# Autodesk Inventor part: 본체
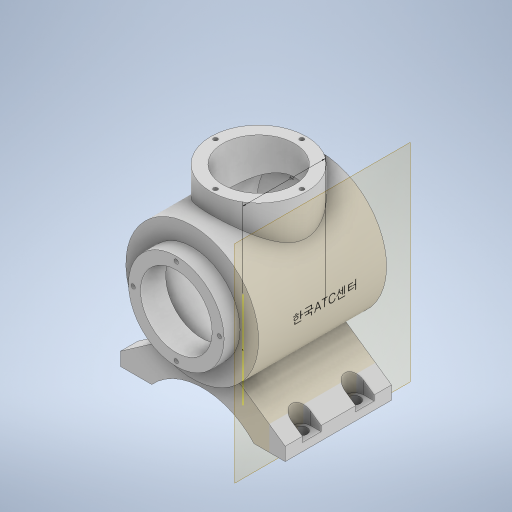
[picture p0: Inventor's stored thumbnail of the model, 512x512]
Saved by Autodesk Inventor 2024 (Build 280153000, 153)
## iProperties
Created: 2023-08
Part Number: 본체
Material: 일반
Document SubType Name: Modeling
Designer: Owner
Density: 1 g/cm^3
Appearance: 기본값
Author: Owner
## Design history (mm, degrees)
sketch "스케치1"
  geometry: L1 (36, 0)-(36, -12); L2 (36, -12)-(50, -12); L3 (50, -12)-(50, -108.336); L4 (0, 0)-(0, -120); L5 (27, -19)-(43, -19); L6 (43, -19)-(43, -103.887); L7 (27, -19)-(27, 0); L8 (27, 0)-(36, 0); A1 r 113 centre (0, -7) between (0, -120) and (50, -108.336); A2 r 106 centre (0, -7) between (0, -113) and (43, -103.887)
  constraints: 16 end point, 4 perpendicular, 4 point on circle, 2 centre point, 2 point on line, 2 vertical, 1 horizontal alignment, 2 other
  dimensions: "d0" = 100 diameter of L3 L4; "d1" = 72 diameter of L1 L4; "d2" = 113 radius of A1; "d5" = 7 radial gap between concentric circles of A1 A2; "d6" = 54 diameter of L7 L4; "d7" = 120 vertical distance of L4.end L1.start; "d9" = 108 distance from line of L4.end L2
revolve "회전1" sketch "스케치1" stored, may be unused: angle "d8" = 90 deg
node "작업 평면1"
sketch "스케치2"
  geometry: C1 r 36 at (0, -62); 1 further point
  constraints: 1 centre point, 1 vertical alignment
  dimensions: "d11" = 72 diameter of C1; "d12" = 62 distance of point (0, 0) C1.centre
extrude "돌출1" join sketch "스케치2" stored distance "d13" = 10; taper "d14" = 0 deg
sketch "스케치3"
  geometry: C1 r 36 at (0, 0) reference; C2 r 27 at (0, 0); 1 further point
  constraints: 1 centre point, 1 coincident
  dimensions: "d15" = 54 diameter of C2
extrude "돌출2" cut sketch "스케치3" stored distance "d16" = 10; taper "d17" = 0 deg
node "작업 평면2"
sketch "스케치4"
  geometry: L1 (-26.694, -42.278)-(-62, -67); L2 (-62, -67)-(-62, -77); L3 (62, -77)-(62, -67); L4 (62, -67)-(26.694, -42.278); L5 (36, 65)-(-36, 65) reference; L6 (-62, -77)-(-38.5, -77); L7 (38.5, -77)-(62, -77); A1 r 50 centre (0, 0) between (26.694, -42.278) and (-26.694, -42.278) reference; A2 r 52.096 centre (0, -112.096) between (38.5, -77) and (-38.5, -77); 3 further points
  constraints: 12 end point, 5 point on circle, 3 horizontal alignment, 2 equal length, 2 perpendicular, 2 vertical, 2 vertical alignment, 1 centre point
  dimensions: "d19" = 55 deg angle of L3 L4; "d20" = 10 distance of L3.start L3.end; "d21" = 124 distance of L2.end L3.start; "d23" = 77 distance of L7.start L6.end; "d24" = 17 distance of point (0, -77) point (0, -60); "d25" = 142 distance between parallel lines of L7 L5
extrude "돌출3" join sketch "스케치4" distance "d26" = 80; taper "d27" = 0 deg
sketch "스케치5"
  geometry: L1 (23.5, 0)-(23.5, -80) reference; L2 (11.5, 8)-(11.5, -88.336) reference; C1 r 4.5 at (15.5, -20); 2 further points
  constraints: 1 centre point, 1 midpoint
  dimensions: "d33" = 8 distance from line of L1 C1.centre; "d34" = 20 vertical distance of point (23.5, -40) C1.centre; "d35" = 9 diameter of C1
extrude "돌출4" cut sketch "스케치5" distance "d36" = 6; taper "d37" = 0 deg
sketch "스케치6"
  geometry: L1 (0, -7)-(8, -7); L2 (8, 7)-(0, 7); L3 (8, 20)-(8, -60) reference; C1 r 4.5 at (0, 0) reference; A1 r 7 centre (0, 0) between (0, 7) and (0, -7); 3 further points
  constraints: 4 end point, 2 midpoint, 2 point on circle, 2 point on line, 2 tangent, 1 centre point, 1 coincident, 1 horizontal, 1 parallel
  dimensions: "d38" = 14 distance of point (4, -7) point (4, 7)
extrude "돌출5" cut sketch "스케치6" stored distance "d39" = 0; taper "d40" = 0 deg
sketch "스케치7"
  geometry: 2 further points
  constraints: 1 vertical alignment
  dimensions: "d44" = 32.5 distance of point (0, 0) point (0, 32.5)
hole "구멍1" sketch "스케치7" at (0, 32.5) diameter "d45" = 3.242; stored, may be unused: countersink angle "d49" = 90 deg, drill point angle "d51" = 118 deg; dims "d46" = 8, "d47" = 4, "d48" = 2, "d50" = 10
sketch "스케치8"
  geometry: C1 r 27 at (0, 0) reference; 2 further points
  constraints: 1 vertical alignment
  dimensions: "d55" = 32.5 distance of C1.centre point (0, 32.5)
hole "구멍2" sketch "스케치8" at (0, 32.5) diameter "d56" = 3.242; stored, may be unused: countersink angle "d60" = 90 deg, drill point angle "d62" = 118 deg; dims "d57" = 8, "d58" = 4, "d59" = 2, "d61" = 10
node "작업 평면3"
sketch "스케치9"
  geometry: L1 (-36, 60.168)-(36, 60.168) reference; 3 further points
  constraints: 1 midpoint, 1 vertical alignment, 1 other
  dimensions: "d66" = 62 distance from line of L1 point (0, -1.832)
node "솔리드1"
mirror "미러1"
pattern_linear "직사각형 패턴1" dims "d43" = 40
pattern_circular "원형 패턴1" dims angle "d53" = 360 deg
pattern_circular "원형 패턴2" dims angle "d64" = 360 deg
feature "A9D066F2-1C7D-4E18-AEED-F7BC21143FA4" dims "d45" = 3.242, "d46" = 8, "d47" = 4, "d48" = 2, "d49" = 90 deg, "d50" = 10, "d51" = 118 deg
other parameters: "d10" = 65, "d22" = 142
